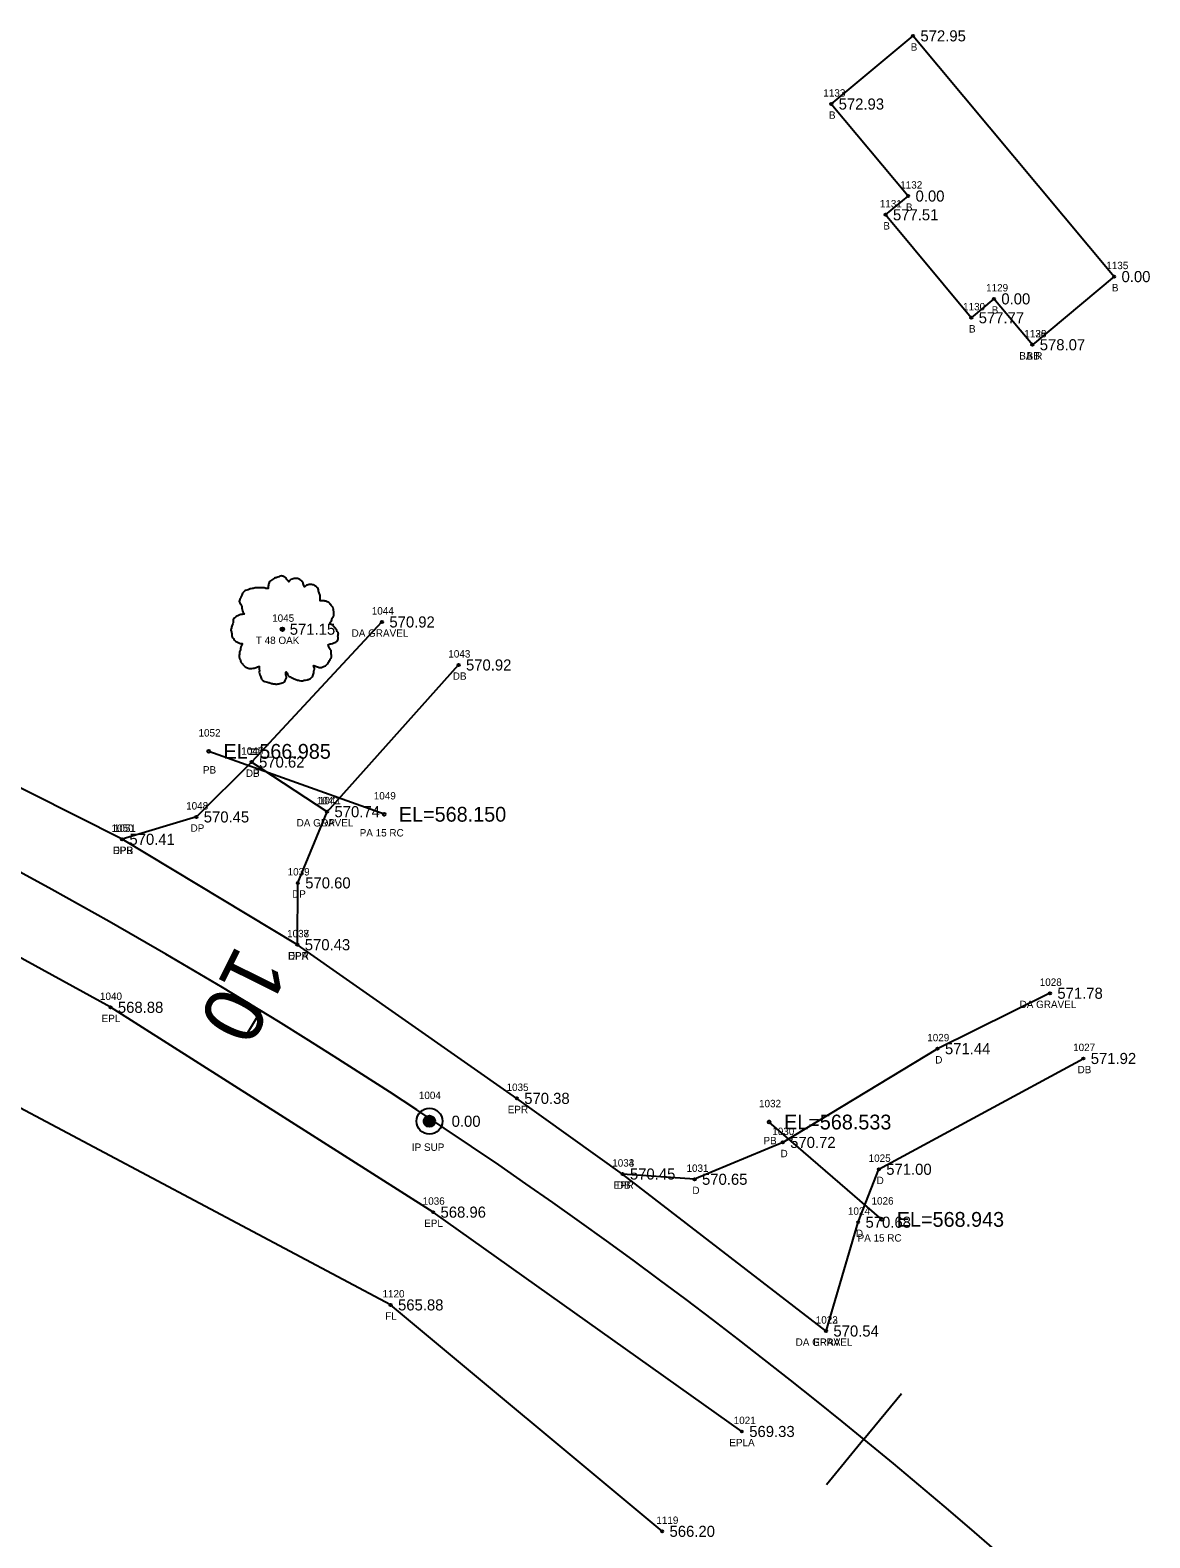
# Model space of a CAD drawing. Extents: x 1529475 to 1532053, y 876698 to 877911.
# Drawn here: x 1531499.1 to 1531650.4, y 877105.9 to 877309.6 of the extents above; entities that cross this region are included whole.
import ezdxf

# ---------------------------------------------------------------- set-up
doc = ezdxf.new("R2010")
doc.units = 0
for name, color, linetype in [('RD_EX_Bldg', 7, 'Continuous'), ('RD_EX_Bldg_txCode', 7, 'Continuous'), ('RD_EX_DR_Pipe', 7, 'Continuous'), ('RD_EX_DR_Pipe_txCode', 7, 'Continuous'), ('RD_EX_Driveway', 7, 'Continuous'), ('RD_EX_Driveway_txCode', 7, 'Continuous'), ('RD_EX_DV_Prop_txCode', 7, 'Continuous'), ('RD_EX_DV_PropPin', 7, 'Continuous'), ('RD_EX_Fence_Other', 7, 'Continuous'), ('RD_EX_Fence_Other_txCode', 7, 'Continuous'), ('RD_EX_Road', 7, 'Continuous'), ('RD_EX_Road_txCode', 7, 'Continuous'), ('RD_EX_TX_Bldg_ELEV', 7, 'Continuous'), ('RD_EX_TX_Driveway_ELEV', 7, 'Continuous'), ('RD_EX_TX_DV_Prop_ELEV', 7, 'Continuous'), ('RD_EX_TX_Fence_Other_ELEV', 7, 'Continuous'), ('RD_EX_TX_Road_ELEV', 7, 'Continuous'), ('RD_EX_TX_VEG_ELEV', 7, 'Continuous'), ('RD_EX_VEG', 7, 'Continuous'), ('RD_EX_VEG_txCode', 7, 'Continuous'), ('RD_HC_Cl', 7, 'Continuous'), ('RD_HC_Data_Tic', 7, 'Continuous'), ('RD_HC_TX_Sta50', 7, 'Continuous'), ('RD_SMD_Locator', 7, 'Continuous'), ('RD_TX_Pipe_ElevEX', 7, 'Continuous')]:
    doc.layers.add(name, color=color, linetype=linetype)

msp = doc.modelspace()

# ---------------------------------------------------------------- linework, layer by layer
at = {"layer": 'RD_EX_Bldg'}
msp.add_lwpolyline([(1531634.52, 877267.08), (1531629.33, 877273.28), (1531626.27, 877270.73), (1531614.69, 877284.64), (1531617.74, 877287.17), (1531607.35, 877299.6), (1531618.4, 877308.81), (1531645.57, 877276.29), (1531634.52, 877267.08)], dxfattribs=at)
at = {"layer": 'RD_EX_DR_Pipe'}
for p, q in [((1531546.93, 877203.65), (1531523.24, 877212.15)), ((1531614.2, 877148.92), (1531598.97, 877162.07))]:
    msp.add_line(p, q, dxfattribs=at)
at = {"layer": 'RD_EX_Driveway'}
for p, q in [((1531546.65, 877229.63), (1531529.04, 877210.7)), ((1531539.23, 877204), (1531557, 877223.82))]:
    msp.add_line(p, q, dxfattribs=at)
for points in [[(1531535.22, 877186.03), (1531535.28, 877194.38), (1531539.23, 877204), (1531529.04, 877210.7), (1531521.57, 877203.29), (1531511.53, 877200.27)], [(1531636.9, 877179.47), (1531621.71, 877171.98), (1531600.8, 877159.32), (1531588.89, 877154.34), (1531579.15, 877155.05)], [(1531606.64, 877133.84), (1531610.98, 877148.54), (1531613.78, 877155.69), (1531641.41, 877170.66)]]:
    msp.add_lwpolyline(points, dxfattribs=at)
at = {"layer": 'RD_EX_DV_PropPin'}
for p, q in [((1531552.36, 877161.88), (1531552.36, 877162.48)), ((1531552.39, 877161.81), (1531552.39, 877162.55)), ((1531552.43, 877161.76), (1531552.43, 877162.61)), ((1531552.46, 877161.71), (1531552.46, 877162.66)), ((1531552.5, 877161.67), (1531552.5, 877162.7)), ((1531552.53, 877161.63), (1531552.53, 877162.73)), ((1531552.57, 877161.6), (1531552.57, 877162.76)), ((1531552.6, 877161.57), (1531552.6, 877162.79)), ((1531552.64, 877161.55), (1531552.64, 877162.82)), ((1531552.67, 877161.53), (1531552.67, 877162.84)), ((1531552.71, 877161.51), (1531552.71, 877162.86)), ((1531552.74, 877161.49), (1531552.74, 877162.88)), ((1531552.78, 877161.48), (1531552.78, 877162.89)), ((1531552.81, 877161.46), (1531552.81, 877162.9)), ((1531552.85, 877161.45), (1531552.85, 877162.91)), ((1531552.88, 877161.44), (1531552.88, 877162.92)), ((1531552.92, 877161.43), (1531552.92, 877162.93)), ((1531552.95, 877161.43), (1531552.95, 877162.94)), ((1531552.99, 877161.43), (1531552.99, 877162.94)), ((1531553.02, 877161.42), (1531553.02, 877162.94)), ((1531553.06, 877161.42), (1531553.06, 877162.94)), ((1531553.09, 877161.42), (1531553.09, 877162.94)), ((1531553.13, 877161.43), (1531553.13, 877162.94)), ((1531553.16, 877161.43), (1531553.16, 877162.94)), ((1531553.2, 877161.43), (1531553.2, 877162.93)), ((1531553.23, 877161.44), (1531553.23, 877162.92)), ((1531553.27, 877161.45), (1531553.27, 877162.91)), ((1531553.3, 877161.46), (1531553.3, 877162.9)), ((1531553.34, 877161.48), (1531553.34, 877162.89)), ((1531553.37, 877161.49), (1531553.37, 877162.88)), ((1531553.41, 877161.51), (1531553.41, 877162.86)), ((1531553.44, 877161.53), (1531553.44, 877162.84)), ((1531553.48, 877161.55), (1531553.48, 877162.82)), ((1531553.51, 877161.57), (1531553.51, 877162.79)), ((1531553.55, 877161.6), (1531553.55, 877162.76)), ((1531553.58, 877161.63), (1531553.58, 877162.73)), ((1531553.62, 877161.67), (1531553.62, 877162.7)), ((1531553.65, 877161.71), (1531553.65, 877162.66)), ((1531553.69, 877161.76), (1531553.69, 877162.61)), ((1531553.72, 877161.81), (1531553.72, 877162.55)), ((1531553.76, 877161.88), (1531553.76, 877162.48)), ((1531552.32, 877161.99), (1531552.32, 877162.38)), ((1531553.79, 877161.99), (1531553.79, 877162.38))]:
    msp.add_line(p, q, dxfattribs=at)
for radius in [1.75, 0.761]:
    msp.add_circle((1531553.06, 877162.18), radius, dxfattribs=at)
at = {"layer": 'RD_EX_Fence_Other'}
msp.add_lwpolyline([(1531584.5, 877106.78), (1531547.82, 877137.37), (1531457.58, 877185.31), (1531406.02, 877209.64), (1531373.66, 877220.15), (1531357.95, 877224.14), (1531321.76, 877233.71), (1531272.23, 877245.59), (1531232.6, 877249.66), (1531180.73, 877254.11), (1531131.27, 877254.15), (1531075.59, 877251.89), (1531032.65, 877249.5), (1530920.26, 877239.27), (1530908.15, 877238.58)], dxfattribs=at)
at = {"layer": 'RD_EX_Road'}
for points in [[(1531606.64, 877133.84), (1531579.15, 877155.05), (1531564.87, 877165.27), (1531535.22, 877186.03), (1531511.53, 877200.27), (1531474.57, 877218.9), (1531430.45, 877239.35), (1531404.48, 877249.38), (1531382.32, 877256.43), (1531333.23, 877270.71), (1531303.67, 877277.44), (1531276.52, 877282.71), (1531237.32, 877287.2), (1531185.8, 877290.94), (1531132.61, 877292.77), (1531081.11, 877292.38), (1531038.69, 877288.67), (1530976.42, 877285.45), (1530941.06, 877284.26)], [(1531595.27, 877120.27), (1531553.56, 877149.9), (1531509.97, 877177.57), (1531465.94, 877201.73), (1531423.65, 877222), (1531376.09, 877237.68), (1531328.84, 877252.31), (1531282.81, 877261.85), (1531235.7, 877268.49), (1531185.47, 877272.84), (1531132.72, 877273.12), (1531080.2, 877271.87), (1531029.21, 877269.53), (1530978.47, 877268.32), (1530945.95, 877265.93), (1530941.45, 877262.44)]]:
    msp.add_lwpolyline(points, dxfattribs=at)
at = {"layer": 'RD_EX_VEG'}
for centre, radius in [((1531533.19, 877228.65), 0.25), ((1531533.18, 877228.63), 0.0001)]:
    msp.add_circle(centre, radius, dxfattribs=at)
for points in [[(1531533.32, 877235.81), (1531533.02, 877235.84), (1531532.7, 877235.74), (1531532.45, 877235.64), (1531532.22, 877235.57), (1531532, 877235.47), (1531531.7, 877235.29), (1531531.47, 877235.09), (1531531.35, 877234.84), (1531531.3, 877234.62), (1531531.25, 877234.34), (1531531.25, 877234.17), (1531531.12, 877234.14), (1531530.97, 877234.17), (1531530.72, 877234.24), (1531530.47, 877234.24), (1531530.22, 877234.24), (1531529.88, 877234.22), (1531529.53, 877234.22), (1531529.25, 877234.17), (1531528.93, 877234.12), (1531528.55, 877233.99), (1531528.2, 877233.87), (1531527.9, 877233.62), (1531527.65, 877233.14), (1531527.53, 877232.79), (1531527.38, 877232.54), (1531527.53, 877232.09), (1531527.7, 877231.74), (1531527.73, 877231.54), (1531527.8, 877231.12), (1531527.9, 877230.89), (1531528.03, 877230.69), (1531527.95, 877230.67), (1531527.58, 877230.62), (1531527.28, 877230.52), (1531526.85, 877230.29), (1531526.63, 877230.07), (1531526.53, 877229.74), (1531526.5, 877229.39), (1531526.4, 877229.19), (1531526.33, 877228.92), (1531526.3, 877228.84), (1531526.25, 877228.52), (1531526.35, 877228.07), (1531526.38, 877227.72), (1531526.5, 877227.49), (1531526.65, 877227.32), (1531526.83, 877227.07), (1531527.23, 877226.84), (1531527.55, 877226.74), (1531527.75, 877226.72), (1531527.58, 877226.22), (1531527.53, 877225.87), (1531527.4, 877225.47), (1531527.4, 877225.39), (1531527.35, 877224.92), (1531527.5, 877224.59), (1531527.58, 877224.22), (1531527.75, 877224), (1531528.03, 877223.7), (1531528.35, 877223.47), (1531528.85, 877223.35), (1531529.25, 877223.37), (1531529.83, 877223.55), (1531530.08, 877223.62), (1531530.05, 877223.45), (1531530.08, 877223.07), (1531530.08, 877222.65), (1531530.22, 877222.32), (1531530.32, 877222.05), (1531530.47, 877221.8), (1531530.8, 877221.57), (1531531.2, 877221.5), (1531531.62, 877221.35), (1531532.07, 877221.27), (1531532.57, 877221.25), (1531533.17, 877221.4), (1531533.45, 877221.52), (1531533.55, 877221.7), (1531533.75, 877222.07), (1531533.7, 877222.3), (1531533.72, 877222.9), (1531533.82, 877222.72), (1531534, 877222.37), (1531534.5, 877222.07), (1531534.9, 877221.9), (1531535.37, 877221.75), (1531535.67, 877221.67), (1531536.15, 877221.75), (1531536.52, 877221.82), (1531536.9, 877221.95), (1531537.2, 877222.22), (1531537.37, 877222.5), (1531537.42, 877222.77), (1531537.5, 877223.15), (1531537.55, 877223.32)], [(1531537.55, 877223.32), (1531537.47, 877223.5), (1531537.42, 877223.75), (1531537.5, 877223.72), (1531537.67, 877223.67), (1531537.95, 877223.55), (1531538.17, 877223.47), (1531538.5, 877223.5), (1531538.77, 877223.6), (1531539.22, 877223.87), (1531539.5, 877224.34), (1531539.77, 877224.74), (1531539.85, 877225.07), (1531539.8, 877225.29), (1531539.77, 877225.79), (1531539.57, 877226.04), (1531539.52, 877226.17), (1531539.42, 877226.57), (1531539.5, 877226.62), (1531539.77, 877226.67), (1531540.15, 877226.79), (1531540.42, 877226.92), (1531540.65, 877227.09), (1531540.72, 877227.32), (1531540.7, 877227.72), (1531540.75, 877228.12), (1531540.67, 877228.27), (1531540.57, 877228.42), (1531540.5, 877228.62), (1531540.35, 877228.77), (1531540.25, 877228.92), (1531540.15, 877229.02), (1531540.02, 877229.17), (1531539.85, 877229.29), (1531539.7, 877229.34), (1531539.65, 877229.49), (1531539.8, 877229.69), (1531539.85, 877229.79), (1531539.87, 877230.02), (1531540.1, 877230.37), (1531540.15, 877230.77), (1531540.1, 877231.19), (1531540.05, 877231.47), (1531539.9, 877231.74), (1531539.7, 877231.99), (1531539.57, 877232.17), (1531539.4, 877232.29), (1531539.07, 877232.42), (1531538.82, 877232.47), (1531538.47, 877232.47), (1531538.27, 877232.52), (1531538.3, 877232.57), (1531538.3, 877232.72), (1531538.3, 877232.99), (1531538.22, 877233.44), (1531538.07, 877233.94), (1531538.07, 877233.97), (1531537.97, 877234.22), (1531537.75, 877234.42), (1531537.57, 877234.52), (1531537.37, 877234.64), (1531537.12, 877234.67), (1531536.82, 877234.67), (1531536.55, 877234.62), (1531536.35, 877234.52), (1531536.17, 877234.39), (1531536.1, 877234.54), (1531536, 877234.84), (1531535.95, 877234.99), (1531535.8, 877235.17), (1531535.57, 877235.37), (1531535.12, 877235.49), (1531534.5, 877235.42), (1531534.2, 877235.22), (1531534.05, 877235.04), (1531534, 877235.17), (1531533.8, 877235.37), (1531533.7, 877235.54), (1531533.52, 877235.67), (1531533.37, 877235.76), (1531533.27, 877235.81)]]:
    msp.add_spline(points, degree=3, dxfattribs=at)
at = {"layer": 'RD_HC_Cl'}
msp.add_arc((1531152.26, 876558.44), 725, 47.4237, 92.33207, dxfattribs=at)
at = {"layer": 'RD_HC_Data_Tic'}
for p, q in [((1531530.29, 877177.09), (1531528.21, 877173.68)), ((1531611.76, 877119.24), (1531616.83, 877125.42)), ((1531611.76, 877119.24), (1531606.69, 877113.05))]:
    msp.add_line(p, q, dxfattribs=at)
at = {"layer": 'RD_SMD_Locator'}
for centre, radius in [((1531618.4, 877308.81), 0.15), ((1531607.35, 877299.6), 0.15), ((1531617.74, 877287.17), 0.15), ((1531614.69, 877284.64), 0.15), ((1531645.57, 877276.29), 0.15), ((1531629.33, 877273.28), 0.15), ((1531626.27, 877270.73), 0.15), ((1531634.52, 877267.08), 0.15), ((1531634.52, 877267.08), 0.15), ((1531546.65, 877229.63), 0.15), ((1531533.19, 877228.65), 0.15), ((1531557, 877223.82), 0.15), ((1531523.24, 877212.15), 0.2), ((1531529.04, 877210.7), 0.15), ((1531529.04, 877210.7), 0.15), ((1531521.57, 877203.29), 0.15), ((1531539.23, 877204), 0.15), ((1531539.23, 877204), 0.15), ((1531546.93, 877203.65), 0.2), ((1531511.53, 877200.27), 0.15), ((1531511.53, 877200.27), 0.15), ((1531535.28, 877194.38), 0.15), ((1531535.22, 877186.03), 0.15), ((1531535.22, 877186.03), 0.15), ((1531636.9, 877179.47), 0.15), ((1531509.97, 877177.57), 0.15), ((1531621.71, 877171.98), 0.15), ((1531641.41, 877170.66), 0.15), ((1531564.87, 877165.27), 0.15), ((1531553.06, 877162.18), 0.15), ((1531598.97, 877162.07), 0.2), ((1531600.8, 877159.32), 0.15), ((1531579.15, 877155.05), 0.15), ((1531579.15, 877155.05), 0.15), ((1531588.89, 877154.34), 0.15), ((1531613.78, 877155.69), 0.15), ((1531553.56, 877149.9), 0.15), ((1531610.98, 877148.54), 0.15), ((1531614.2, 877148.92), 0.2), ((1531547.82, 877137.37), 0.15), ((1531606.64, 877133.84), 0.15), ((1531606.64, 877133.84), 0.15), ((1531595.27, 877120.27), 0.15), ((1531584.5, 877106.78), 0.15)]:
    msp.add_circle(centre, radius, dxfattribs=at)

# ---------------------------------------------------------------- texts
at = {"layer": 'RD_EX_Bldg_txCode'}
for s, p in [('B', (1531618.09, 877306.81)), ('1133', (1531606.28, 877300.6)), ('B', (1531607.04, 877297.6)), ('1132', (1531616.67, 877288.17)), ('1131', (1531613.91, 877285.64)), ('B', (1531617.43, 877285.17)), ('B', (1531614.39, 877282.64)), ('1135', (1531644.51, 877277.29)), ('1129', (1531628.27, 877274.28)), ('B', (1531645.26, 877274.29)), ('1130', (1531625.16, 877271.73)), ('B', (1531629.03, 877271.28)), ('B', (1531625.96, 877268.73)), ('1136', (1531633.43, 877268.08)), ('1128', (1531633.45, 877268.08)), ('BA R', (1531632.76, 877265.08)), ('BB', (1531633.74, 877265.08))]:
    msp.add_text(s, height=1, dxfattribs=at).set_placement(p)
at = {"layer": 'RD_EX_DR_Pipe_txCode'}
for s, p in [('1052', (1531521.86, 877214.15)), ('PB', (1531522.46, 877209.15)), ('1049', (1531545.54, 877205.65)), ('PA 15 RC', (1531543.64, 877200.65)), ('1032', (1531597.59, 877164.07)), ('PB', (1531598.19, 877159.07)), ('1026', (1531612.79, 877150.92)), ('PA 15 RC', (1531610.91, 877145.92))]:
    msp.add_text(s, height=1, dxfattribs=at).set_placement(p)
at = {"layer": 'RD_EX_Driveway_txCode'}
for s, p in [('1044', (1531545.27, 877230.63)), ('DA GRAVEL', (1531542.55, 877227.63)), ('1043', (1531555.61, 877224.82)), ('DB', (1531556.22, 877221.82)), ('1046', (1531527.63, 877211.7)), ('1047', (1531527.65, 877211.7)), ('DB', (1531528.26, 877208.7)), ('DP', (1531528.26, 877208.7)), ('1048', (1531520.19, 877204.29)), ('1042', (1531537.84, 877205)), ('1041', (1531538.12, 877205)), ('1050', (1531510.11, 877201.27)), ('DP', (1531520.79, 877201.29)), ('DA GRAVEL', (1531535.12, 877202)), ('DP', (1531538.45, 877202)), ('DPB', (1531510.28, 877198.27)), ('1039', (1531533.9, 877195.38)), ('DP', (1531534.5, 877192.38)), ('1038', (1531533.83, 877187.03)), ('DPA', (1531533.95, 877184.03)), ('1028', (1531635.52, 877180.47)), ('DA GRAVEL', (1531632.8, 877177.47)), ('1029', (1531620.32, 877172.98)), ('1027', (1531640.03, 877171.66)), ('D', (1531621.4, 877169.98)), ('DB', (1531640.63, 877168.66)), ('1030', (1531599.38, 877160.32)), ('D', (1531600.5, 877157.32)), ('1033', (1531577.76, 877156.05)), ('1031', (1531587.79, 877155.34)), ('1025', (1531612.4, 877156.69)), ('D', (1531613.48, 877153.69)), ('DB', (1531578.37, 877153.05)), ('D', (1531588.59, 877152.34)), ('1024', (1531609.6, 877149.54)), ('D', (1531610.68, 877146.54)), ('1023', (1531605.26, 877134.84)), ('DA GRAVEL', (1531602.54, 877131.84))]:
    msp.add_text(s, height=1, dxfattribs=at).set_placement(p)
at = {"layer": 'RD_EX_DV_Prop_txCode'}
for s, p in [('1004', (1531551.63, 877165.18)), ('IP SUP', (1531550.69, 877158.18))]:
    msp.add_text(s, height=1, dxfattribs=at).set_placement(p)
at = {"layer": 'RD_EX_Fence_Other_txCode'}
for s, p in [('1120', (1531546.72, 877138.37)), ('FL', (1531547.09, 877135.37)), ('1119', (1531583.72, 877107.78))]:
    msp.add_text(s, height=1, dxfattribs=at).set_placement(p)
at = {"layer": 'RD_EX_Road_txCode'}
for s, p in [('1051', (1531510.43, 877201.27)), ('EPR', (1531510.3, 877198.27)), ('1037', (1531533.83, 877187.03)), ('EPR', (1531533.99, 877184.03)), ('1040', (1531508.55, 877178.57)), ('EPL', (1531508.77, 877175.57)), ('1035', (1531563.48, 877166.27)), ('EPR', (1531563.64, 877163.27)), ('1034', (1531577.76, 877156.05)), ('EPR', (1531577.92, 877153.05)), ('1036', (1531552.15, 877150.9)), ('EPL', (1531552.35, 877147.9)), ('1022', (1531605.26, 877134.84)), ('EPRA', (1531604.92, 877131.84)), ('1021', (1531594.17, 877121.27)), ('EPLA', (1531593.58, 877118.27))]:
    msp.add_text(s, height=1, dxfattribs=at).set_placement(p)
at = {"layer": 'RD_EX_TX_Bldg_ELEV'}
for s, p in [('572.95', (1531619.4, 877308.06)), ('572.93', (1531608.35, 877298.85)), ('0.00', (1531618.74, 877286.42)), ('577.51', (1531615.69, 877283.89)), ('0.00', (1531646.57, 877275.54)), ('0.00', (1531630.33, 877272.53)), ('577.77', (1531627.27, 877269.98)), ('578.07', (1531635.52, 877266.33)), ('578.07', (1531635.52, 877266.33))]:
    msp.add_text(s, height=1.5, dxfattribs=at).set_placement(p)
at = {"layer": 'RD_EX_TX_Driveway_ELEV'}
for s, p in [('570.92', (1531547.65, 877228.88)), ('570.92', (1531558, 877223.07)), ('570.62', (1531530.04, 877209.95)), ('570.62', (1531530.04, 877209.95)), ('570.45', (1531522.57, 877202.54)), ('570.74', (1531540.23, 877203.25)), ('570.74', (1531540.23, 877203.25)), ('570.41', (1531512.53, 877199.52)), ('570.60', (1531536.28, 877193.63)), ('570.43', (1531536.22, 877185.28)), ('571.78', (1531637.9, 877178.72)), ('571.44', (1531622.71, 877171.23)), ('571.92', (1531642.41, 877169.91)), ('570.72', (1531601.8, 877158.57)), ('571.00', (1531614.78, 877154.94)), ('570.45', (1531580.15, 877154.3)), ('570.65', (1531589.89, 877153.59)), ('570.68', (1531611.98, 877147.79)), ('570.54', (1531607.64, 877133.09))]:
    msp.add_text(s, height=1.5, dxfattribs=at).set_placement(p)
at = {"layer": 'RD_EX_TX_DV_Prop_ELEV'}
msp.add_text('0.00', height=1.5, dxfattribs=at).set_placement((1531556.06, 877161.43))
at = {"layer": 'RD_EX_TX_Fence_Other_ELEV'}
for s, p in [('565.88', (1531548.82, 877136.62)), ('566.20', (1531585.5, 877106.03))]:
    msp.add_text(s, height=1.5, dxfattribs=at).set_placement(p)
at = {"layer": 'RD_EX_TX_Road_ELEV'}
for s, p in [('570.41', (1531512.53, 877199.52)), ('570.43', (1531536.22, 877185.28)), ('568.88', (1531510.97, 877176.82)), ('570.38', (1531565.87, 877164.52)), ('570.45', (1531580.15, 877154.3)), ('568.96', (1531554.56, 877149.15)), ('570.54', (1531607.64, 877133.09)), ('569.33', (1531596.27, 877119.52))]:
    msp.add_text(s, height=1.5, dxfattribs=at).set_placement(p)
at = {"layer": 'RD_EX_TX_VEG_ELEV'}
msp.add_text('571.15', height=1.5, dxfattribs=at).set_placement((1531534.19, 877227.9))
at = {"layer": 'RD_EX_VEG_txCode'}
for s, p in [('1045', (1531531.81, 877229.65)), ('T 48 OAK', (1531529.61, 877226.65))]:
    msp.add_text(s, height=1, dxfattribs=at).set_placement(p)
at = {"layer": 'RD_HC_TX_Sta50'}
msp.add_text('10', height=8, rotation=243.5971, dxfattribs=at).set_placement((1531527.04, 877186.24))
at = {"layer": 'RD_TX_Pipe_ElevEX'}
for s, p in [('EL=566.985', (1531525.24, 877211.15)), ('EL=568.150', (1531548.93, 877202.65)), ('EL=568.533', (1531600.97, 877161.07)), ('EL=568.943', (1531616.2, 877147.92))]:
    msp.add_text(s, height=2, dxfattribs=at).set_placement(p)

doc.saveas('drawing.dxf')
